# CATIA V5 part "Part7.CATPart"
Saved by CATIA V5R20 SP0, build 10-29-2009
Part number: 1DIN7984516_DIN 7984 - M5 x 16 --- 16C
Revision: ANY
Definition: UNKNOWN
Nomenclature: 1DIN7984516_DIN 7984 - M5 x 16 --- 16C
Source: Unknown
Bounding box of the stored display mesh (mm): x 0 to 19.5, y -4.25 to 4.25, z -4.25 to 4.25
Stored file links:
  C:\Users\Utente\Desktop\IO LAVORO\3D X SITO CF\CUMSA\3D files PW\pw081025\pw081025_injection\Part7.CATPart
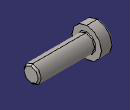
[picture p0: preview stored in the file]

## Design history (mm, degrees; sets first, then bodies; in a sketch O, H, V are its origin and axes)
Body1 "Hex" (main body)
  Solid1: solid without history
